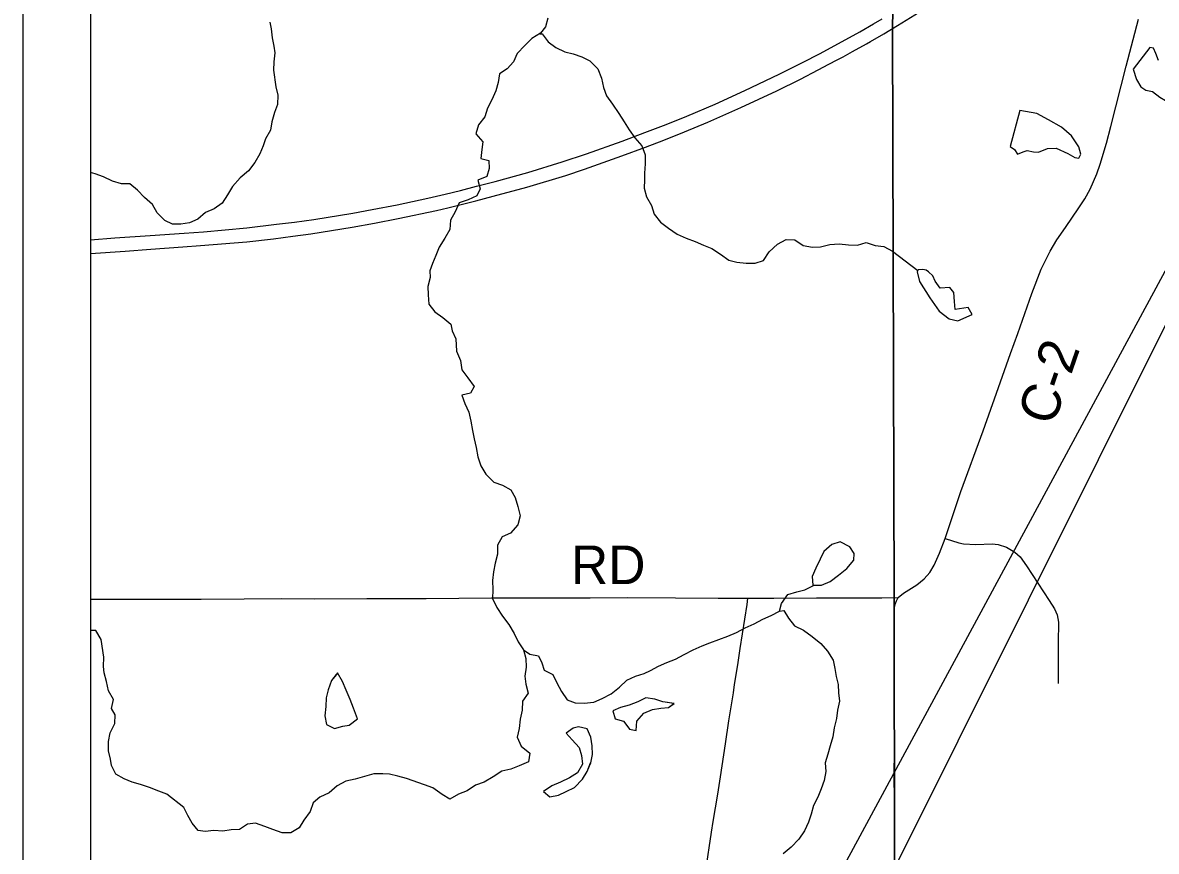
# Model space of a CAD drawing. Extents: x 0 to 34, y 0 to 22.
# Drawn here: x 2 to 3.669, y 14.516 to 15.737 of the extents above; entities that cross this region are included whole.
import ezdxf

# ---------------------------------------------------------------- set-up
doc = ezdxf.new("R2010")
doc.units = 0
for name, color, linetype in [('Default', 7, 'Continuous'), ('GM_X_County_Road', 7, 'Continuous'), ('GM_X_County_Road_Text', 7, 'Continuous'), ('GM_X_Interstate_Route', 7, 'Continuous'), ('GM_X_Minor_Lake', 7, 'Continuous'), ('GM_X_Minor_River', 7, 'Continuous'), ('GM_X_Township_Road', 7, 'Continuous'), ('GM_X_Township_Road_Text', 7, 'Continuous'), ('SH_Cut_Line', 7, 'Continuous'), ('SH_Data', 7, 'Continuous'), ('SH_Text', 7, 'Continuous')]:
    doc.layers.add(name, color=color, linetype=linetype)

msp = doc.modelspace()

# ---------------------------------------------------------------- linework, layer by layer
at = {"layer": 'Default'}
msp.add_lwpolyline([(3.2815, 15.7537), (3.2811, 15.7294), (3.2832, 14.8896), (3.2841, 14.501), (3.2822, 14.2781), (3.2808, 14.1155), (3.2807, 14.1), (8.4439, 14.1), (8.4391, 14.4529), (8.4328, 14.555), (8.4328, 14.5554), (8.4608, 15.4787), (8.4608, 15.9241)], dxfattribs=at)
msp.add_lwpolyline([(2.1, 15.8248), (2.1, 14.1), (3.2807, 14.1), (3.2808, 14.1155), (3.2822, 14.2781), (3.2841, 14.501), (3.2832, 14.8896), (3.2811, 15.7294), (3.2815, 15.7537), (3.2829, 15.8433)], close=True, dxfattribs=at)
at = {"layer": 'GM_X_County_Road'}
for points in [[(3.2894, 14.8897), (3.2972, 14.8963), (3.3169, 14.9086), (3.3276, 14.9175), (3.336, 14.9266), (3.3424, 14.9373), (3.3501, 14.9551), (3.3586, 14.977), (3.3818, 15.0458), (3.4146, 15.1354), (3.434, 15.1907), (3.4545, 15.2493), (3.4656, 15.2789), (3.4862, 15.3379), (3.4997, 15.3734), (3.5131, 15.4002), (3.5228, 15.4169), (3.5355, 15.4351), (3.5554, 15.4639), (3.5641, 15.477), (3.5719, 15.4912), (3.5817, 15.5142), (3.5867, 15.5284), (3.5959, 15.5592), (3.6023, 15.5835), (3.6249, 15.6727), (3.643, 15.7419)], [(3.2821, 14.2674), (3.2822, 14.2949), (3.2824, 14.3323), (3.2833, 14.397), (3.2836, 14.4329), (3.2838, 14.4734), (3.2837, 14.5933), (3.2836, 14.6255), (3.2837, 14.6664), (3.2838, 14.6736), (3.2838, 14.7095), (3.2841, 14.7456), (3.2841, 14.7863), (3.2839, 14.8273), (3.2837, 14.8684), (3.2841, 14.8751), (3.2852, 14.8808), (3.2868, 14.8852), (3.2894, 14.8897)]]:
    msp.add_lwpolyline(points, dxfattribs=at)
at = {"layer": 'GM_X_Interstate_Route'}
for points in [[(3.2884, 15.7323), (3.3713, 15.7839), (3.3812, 15.7905)], [(2.1, 15.4169), (2.1357, 15.4196), (2.1879, 15.4232), (2.2376, 15.4266), (2.2661, 15.4287), (2.3302, 15.4345), (2.3736, 15.4397), (2.4001, 15.4429), (2.4289, 15.4468), (2.4864, 15.4563), (2.5148, 15.4615), (2.5516, 15.4685), (2.5966, 15.4782), (2.6222, 15.4841), (2.645, 15.4896), (2.6684, 15.4957), (2.6957, 15.5027), (2.7439, 15.516), (2.7944, 15.5316), (2.8305, 15.5435), (2.883, 15.5622), (2.9164, 15.5747), (2.9477, 15.5869), (2.9783, 15.5991), (3.0199, 15.6168), (3.0634, 15.6369), (3.1141, 15.6607), (3.1496, 15.6786), (3.1734, 15.691), (3.207, 15.709), (3.233, 15.7234), (3.2528, 15.7349), (3.2659, 15.7423)], [(2.1, 15.3967), (2.1509, 15.4003), (2.1886, 15.4028), (2.2361, 15.4063), (2.2617, 15.4082), (2.33, 15.414), (2.3695, 15.4184), (2.3978, 15.422), (2.4242, 15.4257), (2.4853, 15.4353), (2.5182, 15.4414), (2.5532, 15.4481), (2.6093, 15.4601), (2.6262, 15.4641), (2.644, 15.4685), (2.6674, 15.4742), (2.693, 15.481), (2.7425, 15.4946), (2.7997, 15.5118), (2.8273, 15.5211), (2.8824, 15.5404), (2.9174, 15.5532), (2.9442, 15.5635), (2.9746, 15.5758), (3.009, 15.59), (3.0576, 15.6117), (3.1104, 15.6363), (3.1455, 15.6537), (3.1715, 15.6672), (3.1872, 15.6756), (3.1995, 15.682), (3.2084, 15.6866), (3.2218, 15.694), (3.2425, 15.7057), (3.2484, 15.7089), (3.2683, 15.7205), (3.2884, 15.7323)]]:
    msp.add_lwpolyline(points, dxfattribs=at)
at = {"layer": 'GM_X_Minor_Lake'}
for points in [[(3.6727, 15.6811), (3.6688, 15.6914), (3.6653, 15.6989), (3.66, 15.7), (3.6353, 15.6682), (3.6403, 15.6531), (3.6465, 15.6421), (3.6541, 15.6373), (3.6636, 15.6351), (3.6747, 15.6268), (3.6831, 15.622), (3.6865, 15.6224), (3.7121, 15.6488)], [(3.4541, 15.5545), (3.4606, 15.55), (3.4652, 15.5432), (3.4732, 15.5463), (3.4792, 15.5486), (3.4884, 15.5464), (3.496, 15.5457), (3.5092, 15.5512), (3.5221, 15.5517), (3.5389, 15.5439), (3.5492, 15.5379), (3.5552, 15.5372), (3.5582, 15.5429), (3.5555, 15.5539), (3.5443, 15.5698), (3.5298, 15.5829), (3.5107, 15.5937), (3.4935, 15.6031), (3.4685, 15.6074)], [(3.4685, 15.6074), (3.4541, 15.5545)], [(3.334, 15.3698), (3.3307, 15.3722), (3.3281, 15.3728), (3.3249, 15.3729), (3.3186, 15.3726), (3.3173, 15.3697)], [(3.3173, 15.3697), (3.3205, 15.3553), (3.3359, 15.3315), (3.3497, 15.3115), (3.3646, 15.3006), (3.3771, 15.2977), (3.3983, 15.3066), (3.3922, 15.3172), (3.3732, 15.314), (3.3723, 15.3261), (3.3711, 15.3394), (3.3653, 15.3466), (3.3513, 15.3457), (3.344, 15.3559), (3.3405, 15.3638), (3.334, 15.3698)], [(3.2246, 14.9549), (3.218, 14.9646), (3.2039, 14.9718), (3.1914, 14.968), (3.1796, 14.9577), (3.1743, 14.9463), (3.1682, 14.9333), (3.1625, 14.9208), (3.1637, 14.9082), (3.1688, 14.9081)], [(3.1688, 14.9081), (3.1766, 14.9079), (3.1892, 14.9136), (3.2013, 14.9227), (3.2135, 14.9326), (3.2241, 14.9448), (3.2246, 14.9549)], [(3.1688, 14.9081), (3.1766, 14.9079), (3.1892, 14.9136), (3.2013, 14.9227), (3.2135, 14.9326), (3.2241, 14.9448), (3.2246, 14.9549)], [(2.4616, 14.7762), (2.4546, 14.7674), (2.4497, 14.7537), (2.4471, 14.7423), (2.4463, 14.7294), (2.4452, 14.7157), (2.4475, 14.7028), (2.4593, 14.6971), (2.4715, 14.7001), (2.481, 14.7017), (2.4929, 14.7109)], [(2.4615, 14.7761), (2.4546, 14.7674), (2.4497, 14.7537), (2.4471, 14.7423), (2.4463, 14.7294), (2.4452, 14.7157), (2.4475, 14.7028), (2.4593, 14.6971), (2.4715, 14.7001), (2.481, 14.7017), (2.4929, 14.7109)], [(2.4929, 14.7109), (2.487, 14.7268), (2.4825, 14.7397), (2.4764, 14.7534), (2.471, 14.7663), (2.4638, 14.7788), (2.4615, 14.7761)], [(2.4929, 14.7109), (2.487, 14.7268), (2.4825, 14.7397), (2.4764, 14.7534), (2.471, 14.7663), (2.4638, 14.7788), (2.4615, 14.7761)], [(2.9591, 14.7337), (2.9429, 14.7361), (2.9307, 14.7399), (2.9177, 14.7421), (2.906, 14.7364), (2.893, 14.7315), (2.8805, 14.7276), (2.8691, 14.7227), (2.8725, 14.7109), (2.8847, 14.7079), (2.8881, 14.7034)], [(2.9592, 14.7337), (2.9429, 14.7361), (2.9307, 14.7399), (2.9177, 14.7421), (2.906, 14.7364), (2.893, 14.7315), (2.8805, 14.7276), (2.8691, 14.7227), (2.8725, 14.7109), (2.8847, 14.7079), (2.8881, 14.7034)], [(2.888, 14.7033), (2.8938, 14.6957), (2.9034, 14.6938), (2.9045, 14.7075), (2.9147, 14.7193), (2.9277, 14.725), (2.9398, 14.7266), (2.9512, 14.7277), (2.9592, 14.7338)], [(2.8881, 14.7034), (2.8938, 14.6957), (2.9034, 14.6938), (2.9045, 14.7075), (2.9147, 14.7193), (2.9277, 14.725), (2.9398, 14.7266), (2.9512, 14.7277), (2.9591, 14.7337)], [(2.8185, 14.6992), (2.8105, 14.6975), (2.8002, 14.6899), (2.8094, 14.6804), (2.8193, 14.669), (2.8231, 14.6569), (2.8243, 14.6443), (2.8171, 14.6317), (2.8053, 14.6241), (2.792, 14.6176), (2.7791, 14.6123), (2.7669, 14.6039), (2.7764, 14.596), (2.789, 14.5986), (2.8004, 14.6043), (2.8125, 14.6101), (2.8243, 14.6223), (2.8311, 14.6337), (2.8364, 14.6461)], [(2.8186, 14.6992), (2.8105, 14.6975), (2.8002, 14.6899), (2.8094, 14.6804), (2.8193, 14.669), (2.8231, 14.6569), (2.8243, 14.6443), (2.8171, 14.6317), (2.8053, 14.6241), (2.792, 14.6176), (2.7791, 14.6123), (2.7669, 14.6039), (2.7764, 14.596), (2.789, 14.5986), (2.8004, 14.6043), (2.8125, 14.6101), (2.8243, 14.6223), (2.8311, 14.6337), (2.8347, 14.6421)], [(2.8364, 14.6461), (2.8365, 14.6462), (2.8391, 14.6584), (2.8387, 14.6713), (2.8368, 14.6839), (2.8311, 14.6964), (2.8185, 14.6992)], [(2.8347, 14.6421), (2.8365, 14.6462), (2.8391, 14.6584), (2.8387, 14.6713), (2.8368, 14.6839), (2.8311, 14.6964), (2.8187, 14.6991)]]:
    msp.add_lwpolyline(points, dxfattribs=at)
at = {"layer": 'GM_X_Minor_River'}
for points in [[(2.7732, 15.7435), (2.7698, 15.7306), (2.7626, 15.7211), (2.75, 15.7134), (2.7394, 15.7032), (2.7284, 15.6914), (2.7227, 15.6788), (2.7136, 15.6689), (2.7021, 15.6613), (2.7003, 15.6484), (2.6969, 15.6362), (2.6908, 15.6229), (2.6847, 15.6107), (2.6806, 15.5978), (2.6711, 15.586), (2.6673, 15.573), (2.6776, 15.5612), (2.6764, 15.5498), (2.6749, 15.5365), (2.6867, 15.5339), (2.6871, 15.5217), (2.6833, 15.5099), (2.6704, 15.5046), (2.6739, 15.492), (2.6686, 15.4814), (2.656, 15.4757), (2.6427, 15.4711), (2.637, 15.4581), (2.6302, 15.4456), (2.6291, 15.4319), (2.6215, 15.4193), (2.6131, 15.406), (2.6082, 15.3938), (2.6036, 15.3821), (2.5995, 15.371), (2.5999, 15.3615), (2.5965, 15.3478), (2.5972, 15.3357), (2.598, 15.322), (2.6072, 15.3106), (2.6186, 15.3026), (2.6304, 15.2924), (2.6327, 15.2829), (2.638, 15.2707)], [(2.3642, 15.7373), (2.3661, 15.7278), (2.3672, 15.7145), (2.3699, 15.7019), (2.3715, 15.6924), (2.37, 15.6791), (2.3692, 15.6666), (2.373, 15.6422), (2.3757, 15.6297), (2.3754, 15.616), (2.3708, 15.6042), (2.3667, 15.5905), (2.3652, 15.5783), (2.3576, 15.5658), (2.3542, 15.5555), (2.3492, 15.5433), (2.342, 15.5308), (2.3325, 15.5186), (2.3204, 15.5083), (2.309, 15.4954), (2.3014, 15.4832), (2.2938, 15.4706), (2.282, 15.4626), (2.2694, 15.4569), (2.258, 15.447), (2.2459, 15.4417), (2.2329, 15.4401), (2.2208, 15.4401), (2.2093, 15.4454), (2.1983, 15.4564), (2.191, 15.469), (2.1792, 15.4792), (2.1689, 15.4899), (2.1579, 15.4994), (2.1457, 15.4993), (2.1324, 15.5031), (2.1191, 15.5096), (2.1069, 15.5141), (2.1, 15.516)], [(2.7614, 15.7204), (2.7648, 15.7203), (2.774, 15.7085), (2.785, 15.7002), (2.7984, 15.6937), (2.8105, 15.6907), (2.8235, 15.6862), (2.8353, 15.6805), (2.8471, 15.6687), (2.8525, 15.655), (2.8555, 15.6413), (2.8597, 15.6288), (2.8685, 15.6166), (2.878, 15.603), (2.886, 15.5904), (2.8929, 15.5786), (2.9013, 15.5672), (2.912, 15.5551), (2.9165, 15.5422), (2.9169, 15.5285), (2.9158, 15.5148), (2.9155, 15.5053), (2.9151, 15.4931), (2.9185, 15.4802), (2.9258, 15.4676), (2.93, 15.4547), (2.9395, 15.4429), (2.9509, 15.4342), (2.9639, 15.4251), (2.9772, 15.419), (2.9902, 15.4141), (3.0024, 15.4088), (3.0149, 15.4039), (3.0275, 15.3959), (3.0401, 15.3868), (3.0515, 15.3838), (3.0652, 15.3823), (3.0789, 15.3823), (3.091, 15.3865), (3.0994, 15.399), (3.1116, 15.4105), (3.1241, 15.4173), (3.137, 15.4166), (3.1496, 15.4086), (3.1629, 15.406), (3.1751, 15.4064), (3.1888, 15.4098), (3.2025, 15.411), (3.2162, 15.4095), (3.2295, 15.4091), (3.2421, 15.4129), (3.2554, 15.4084), (3.2683, 15.4069), (3.2809, 15.3999)], [(3.2808, 15.3999), (3.3182, 15.3716)], [(2.638, 15.2707), (2.6388, 15.2528), (2.6449, 15.2391), (2.6469, 15.2255), (2.6556, 15.2137), (2.6648, 15.2008), (2.6595, 15.1909), (2.6469, 15.1878), (2.6511, 15.1756), (2.6572, 15.1627), (2.6599, 15.1498), (2.6626, 15.1361), (2.6649, 15.1236), (2.668, 15.1107), (2.6703, 15.097), (2.6745, 15.0837), (2.6821, 15.0715), (2.6939, 15.0597), (2.7065, 15.0552), (2.7187, 15.0487), (2.7255, 15.0373), (2.7294, 15.0237), (2.7324, 15.01), (2.729, 14.997), (2.7184, 14.9845), (2.7062, 14.9791), (2.6994, 14.967), (2.699, 14.9537), (2.6956, 14.9407), (2.6934, 14.9278), (2.6918, 14.9149), (2.6922, 14.9012), (2.6919, 14.8882), (2.6984, 14.8753), (2.7068, 14.8624), (2.7159, 14.8499), (2.7239, 14.837), (2.7297, 14.8244), (2.7377, 14.8126)], [(3.1146, 14.8698), (3.1173, 14.8812), (3.1268, 14.8945), (3.1401, 14.8983), (3.1519, 14.9014), (3.1655, 14.9082)], [(2.7377, 14.8126), (2.7468, 14.8066), (2.7594, 14.8039), (2.7647, 14.7937), (2.7681, 14.783), (2.7807, 14.7766), (2.7868, 14.764), (2.7933, 14.7515), (2.8017, 14.739), (2.8135, 14.7348), (2.8268, 14.7344), (2.8409, 14.7356), (2.8534, 14.7409), (2.8664, 14.7478), (2.8789, 14.7577), (2.8895, 14.768), (2.9025, 14.7741), (2.915, 14.7779), (2.9245, 14.7825), (2.9363, 14.7889), (2.9485, 14.7943), (2.9614, 14.7992), (2.974, 14.8057), (2.9873, 14.813), (3.0006, 14.8187), (3.012, 14.8229), (3.0386, 14.8328), (3.0511, 14.8385), (3.0641, 14.8454), (3.0774, 14.8511), (3.0899, 14.8579), (3.1021, 14.8633), (3.1146, 14.8698)], [(3.1146, 14.8698), (3.1207, 14.8705), (3.1276, 14.8595), (3.1364, 14.8481), (3.1497, 14.8417), (3.1626, 14.8322), (3.1752, 14.8223), (3.1851, 14.8109), (3.1935, 14.7976), (3.1958, 14.7851), (3.1981, 14.7737), (3.2008, 14.7615), (3.2012, 14.7493), (3.2027, 14.7372), (3.2001, 14.7239), (3.1986, 14.7117), (3.1952, 14.698), (3.1929, 14.6847), (3.1891, 14.6714), (3.1857, 14.6592), (3.1819, 14.6463), (3.1827, 14.6333), (3.1805, 14.6204), (3.1759, 14.6079), (3.171, 14.5957), (3.1645, 14.5835), (3.1611, 14.5706), (3.157, 14.5588), (3.1513, 14.5459), (3.1429, 14.5341), (3.1319, 14.5223), (3.1201, 14.5124)], [(2.7377, 14.8126), (2.7411, 14.8001), (2.7415, 14.7872), (2.7396, 14.7742), (2.7412, 14.7621), (2.7446, 14.7488), (2.7359, 14.7374), (2.7355, 14.7237), (2.7325, 14.7107), (2.731, 14.697), (2.728, 14.6841), (2.7341, 14.6708), (2.747, 14.6606), (2.7448, 14.648), (2.7311, 14.6419), (2.7189, 14.6369), (2.7056, 14.6339), (2.693, 14.6255), (2.6797, 14.6179), (2.6668, 14.6133), (2.6546, 14.6049), (2.6417, 14.6003), (2.6292, 14.5927), (2.6177, 14.5999), (2.604, 14.6094), (2.5918, 14.614), (2.5652, 14.6231), (2.5523, 14.6269), (2.5401, 14.6295), (2.5306, 14.6302), (2.5169, 14.6299), (2.4895, 14.6222), (2.4758, 14.6195), (2.4632, 14.6123), (2.4515, 14.602), (2.4378, 14.5955), (2.4279, 14.5875), (2.4233, 14.5746), (2.4139, 14.562), (2.407, 14.5506), (2.3949, 14.5434), (2.3819, 14.5434), (2.3686, 14.5483), (2.3564, 14.5525), (2.3427, 14.5574), (2.3313, 14.5562), (2.3191, 14.5479), (2.307, 14.5475), (2.2948, 14.5455), (2.2815, 14.5467), (2.2685, 14.5451), (2.2583, 14.5466), (2.2495, 14.5573), (2.243, 14.5687), (2.2373, 14.5805), (2.2125, 14.6002), (2.2003, 14.6044), (2.187, 14.61), (2.1737, 14.6142), (2.1611, 14.6176), (2.1493, 14.6225), (2.1371, 14.6294), (2.131, 14.6423), (2.1291, 14.6518), (2.1264, 14.664), (2.1264, 14.6777), (2.1287, 14.6906), (2.1355, 14.7043), (2.1362, 14.7168), (2.1309, 14.7263), (2.1339, 14.7396), (2.1263, 14.7522), (2.1236, 14.7659), (2.1198, 14.7788), (2.119, 14.7883), (2.1194, 14.802), (2.1155, 14.8278), (2.1079, 14.8411), (2.1, 14.8413)]]:
    msp.add_lwpolyline(points, dxfattribs=at)
at = {"layer": 'GM_X_Township_Road'}
for points in [[(3.3586, 14.977), (3.3784, 14.9705), (3.3855, 14.9687), (3.4035, 14.9681), (3.4276, 14.9687), (3.4364, 14.9678), (3.4488, 14.964), (3.4609, 14.9569), (3.4691, 14.9498), (3.4782, 14.9366), (3.5115, 14.8854), (3.5197, 14.873), (3.5233, 14.8642), (3.5253, 14.8533), (3.5247, 14.823), (3.5248, 14.7632)], [(2.1, 14.8873), (2.1001, 14.8873), (2.1526, 14.8872), (2.1935, 14.8873), (2.2629, 14.8872), (2.326, 14.8878), (2.3807, 14.8884), (2.4296, 14.8878), (2.5069, 14.8883), (2.5452, 14.8884), (2.594, 14.8886), (2.6902, 14.8893), (2.7273, 14.8892), (2.7733, 14.8894), (2.8359, 14.8896), (2.89, 14.8897), (2.9615, 14.8893), (3.0243, 14.889), (3.0677, 14.8888), (3.1063, 14.889), (3.1689, 14.8894), (3.2322, 14.8895), (3.265, 14.8896), (3.2894, 14.8897)], [(3.006, 14.4883), (3.0146, 14.5441), (3.017, 14.5598), (3.0235, 14.6002), (3.0275, 14.6259), (3.0351, 14.6742), (3.0401, 14.7081), (3.0467, 14.7496), (3.0485, 14.7616), (3.0531, 14.7906), (3.0568, 14.8147), (3.0667, 14.8798), (3.0677, 14.8888)]]:
    msp.add_lwpolyline(points, dxfattribs=at)
at = {"layer": 'SH_Cut_Line'}
for points in [[(3.2826, 20.9), (2.1, 20.9), (2.1, 14.1), (3.2807, 14.1), (3.2808, 14.1155), (3.2822, 14.2781), (3.2841, 14.501), (3.2832, 14.8896), (3.2811, 15.7294), (3.2815, 15.7537), (3.2829, 15.8433), (3.2832, 16.3898), (3.2835, 17.0107), (3.2837, 17.3796), (3.2907, 18.4315), (3.2904, 19.1173), (3.2901, 19.68), (3.2888, 19.8918), (3.2845, 20.5998), (3.2843, 20.6124)], [(3.2807, 14.1), (8.9, 14.1), (8.9, 20.9), (3.2826, 20.9), (3.2843, 20.6124), (3.2845, 20.5998), (3.2888, 19.8918), (3.2901, 19.68), (3.2904, 19.1173), (3.2907, 18.4315), (3.2837, 17.3796), (3.2835, 17.0107), (3.2832, 16.3898), (3.2829, 15.8433), (3.2815, 15.7537), (3.2811, 15.7294), (3.2832, 14.8896), (3.2841, 14.501), (3.2822, 14.2781), (3.2808, 14.1155)]]:
    msp.add_lwpolyline(points, close=True, dxfattribs=at)
at = {"layer": 'SH_Data'}
for p, q in [((2, 21), (2, 14)), ((2.1, 20.9), (2.1, 14.1))]:
    msp.add_line(p, q, dxfattribs=at)
at = {"layer": 'SH_Text'}
msp.add_lwpolyline([(2.8604, 13.8477), (4.2041, 16.3374), (2.8604, 13.6417)], close=True, dxfattribs=at)

# ---------------------------------------------------------------- texts
at = {"layer": 'GM_X_County_Road_Text'}
msp.add_text('C-2', height=0.05682, rotation=71.0057, dxfattribs=at).set_placement((3.5177, 15.1409))
at = {"layer": 'GM_X_Township_Road_Text'}
msp.add_text('RD', height=0.05682, rotation=0, dxfattribs=at).set_placement((2.8074, 14.9096))

doc.saveas('drawing.dxf')
